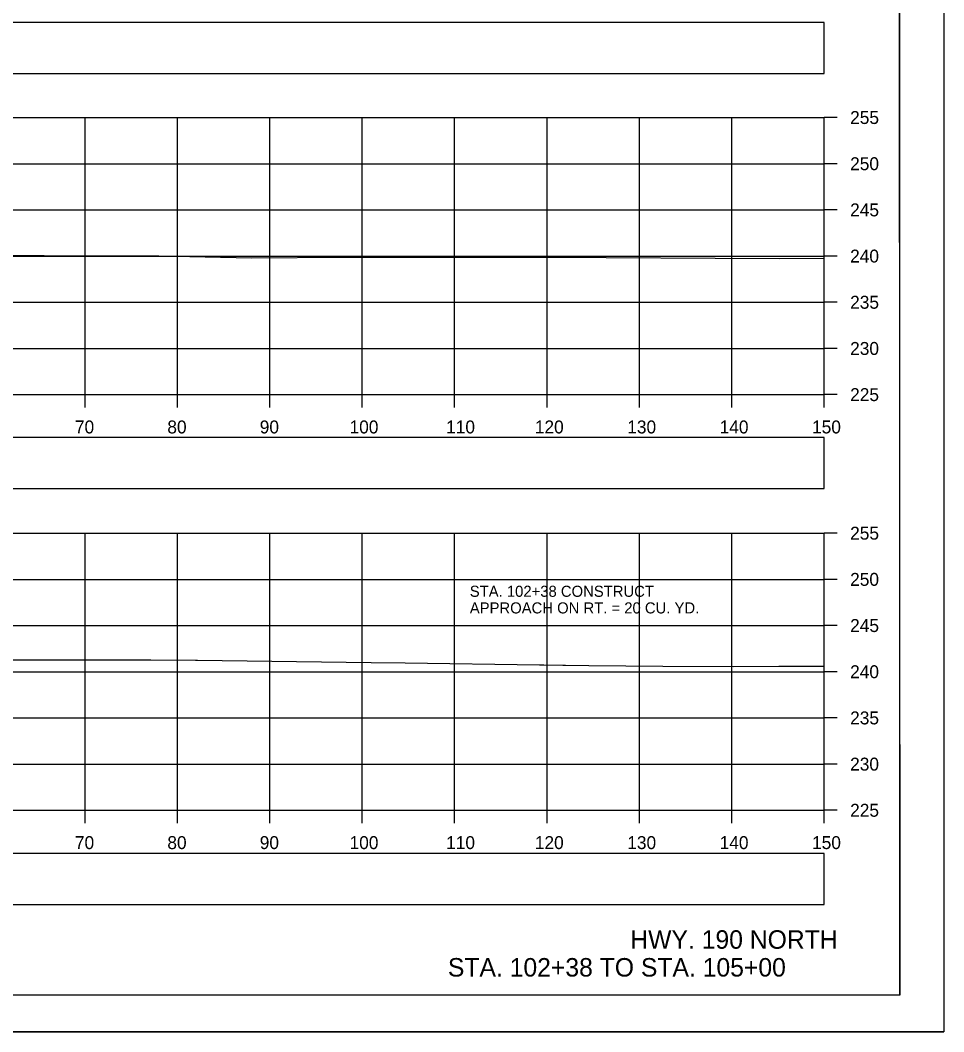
# Model space of a CAD drawing. Extents: x 1369627 to 1374022, y 380035 to 398173.
# Drawn here: x 1370242.2 to 1370342.2, y 380248.2 to 380357.7 of the extents above; entities that cross this region are included whole.
import ezdxf

# ---------------------------------------------------------------- set-up
doc = ezdxf.new("R2010")
doc.units = 0
for name, color, linetype in [('Default', 7, 'Continuous'), ('R_Axis', 7, 'Continuous'), ('R_Axis Annot', 7, 'Continuous'), ('R_Border', 7, 'Continuous'), ('R_Draft', 7, 'Continuous'), ('R_Exist Surface', 7, 'Continuous'), ('R_Grid', 7, 'Continuous'), ('R_No Plot', 7, 'Continuous'), ('R_Water', 7, 'Continuous')]:
    doc.layers.add(name, color=color, linetype=linetype)

msp = doc.modelspace()

# ---------------------------------------------------------------- linework, layer by layer
at = {"layer": 'Default'}
for points in [[(1370029.24, 380351.95), (1370329.24, 380351.95), (1370329.24, 380357.47), (1370029.24, 380357.47)], [(1370029.24, 380307.01), (1370329.24, 380307.01), (1370329.24, 380312.54), (1370029.24, 380312.54)], [(1370029.24, 380261.98), (1370329.24, 380261.98), (1370329.24, 380267.5), (1370029.24, 380267.5)]]:
    msp.add_lwpolyline(points, close=True, dxfattribs=at)
at = {"layer": 'R_Axis'}
for p, q in [((1370329.24, 380317.19), (1370329.24, 380347.19)), ((1370330.64, 380347.19), (1370329.24, 380347.19)), ((1370330.64, 380342.19), (1370329.24, 380342.19)), ((1370330.64, 380337.19), (1370329.24, 380337.19)), ((1370330.64, 380332.19), (1370329.24, 380332.19)), ((1370330.64, 380327.19), (1370329.24, 380327.19)), ((1370330.64, 380322.19), (1370329.24, 380322.19)), ((1370029.24, 380317.19), (1370329.24, 380317.19)), ((1370249.24, 380315.79), (1370249.24, 380317.19)), ((1370259.24, 380315.79), (1370259.24, 380317.19)), ((1370269.24, 380315.79), (1370269.24, 380317.19)), ((1370279.24, 380315.79), (1370279.24, 380317.19)), ((1370289.24, 380315.79), (1370289.24, 380317.19)), ((1370299.24, 380315.79), (1370299.24, 380317.19)), ((1370309.24, 380315.79), (1370309.24, 380317.19)), ((1370319.24, 380315.79), (1370319.24, 380317.19)), ((1370329.24, 380315.79), (1370329.24, 380317.19)), ((1370330.64, 380317.19), (1370329.24, 380317.19)), ((1370329.24, 380272.19), (1370329.24, 380302.19)), ((1370330.64, 380302.19), (1370329.24, 380302.19)), ((1370330.64, 380297.19), (1370329.24, 380297.19)), ((1370330.64, 380292.19), (1370329.24, 380292.19)), ((1370330.64, 380287.19), (1370329.24, 380287.19)), ((1370330.64, 380282.19), (1370329.24, 380282.19)), ((1370330.64, 380277.19), (1370329.24, 380277.19)), ((1370029.24, 380272.19), (1370329.24, 380272.19)), ((1370249.24, 380270.79), (1370249.24, 380272.19)), ((1370259.24, 380270.79), (1370259.24, 380272.19)), ((1370269.24, 380270.79), (1370269.24, 380272.19)), ((1370279.24, 380270.79), (1370279.24, 380272.19)), ((1370289.24, 380270.79), (1370289.24, 380272.19)), ((1370299.24, 380270.79), (1370299.24, 380272.19)), ((1370309.24, 380270.79), (1370309.24, 380272.19)), ((1370319.24, 380270.79), (1370319.24, 380272.19)), ((1370329.24, 380270.79), (1370329.24, 380272.19)), ((1370330.64, 380272.19), (1370329.24, 380272.19))]:
    msp.add_line(p, q, dxfattribs=at)
at = {"layer": 'R_Border'}
for q in [(1370337.42, 380457.65), (1370021.24, 380252.19)]:
    msp.add_line((1370337.42, 380252.19), q, dxfattribs=at)
at = {"layer": 'R_Exist Surface'}
for points in [[(1370240.95, 380332.3), (1370248.69, 380332.2), (1370257.05, 380332.21), (1370257.13, 380332.21), (1370257.24, 380332.21), (1370267.27, 380332.01), (1370277.18, 380332.09), (1370287.06, 380332.08), (1370291.38, 380332.06), (1370301.45, 380332.06), (1370305.63, 380332.03), (1370317.45, 380331.96), (1370324.4, 380331.94), (1370329.24, 380331.96)], [(1370233.09, 380288.49), (1370246.11, 380288.48), (1370246.74, 380288.48), (1370247.13, 380288.48), (1370256.38, 380288.47), (1370261.19, 380288.43), (1370261.29, 380288.43), (1370261.34, 380288.43), (1370261.43, 380288.43), (1370277.51, 380288.22), (1370280.2, 380288.18), (1370283.88, 380288.14), (1370298.44, 380287.95), (1370298.88, 380287.92), (1370300.94, 380287.89), (1370301.25, 380287.89), (1370303.78, 380287.86), (1370311.77, 380287.81), (1370319.45, 380287.76), (1370324.33, 380287.8), (1370327.04, 380287.79), (1370329.24, 380287.79)]]:
    msp.add_lwpolyline(points, dxfattribs=at)
at = {"layer": 'R_Grid'}
for p, q in [((1370029.24, 380347.19), (1370329.24, 380347.19)), ((1370249.24, 380317.19), (1370249.24, 380347.19)), ((1370259.24, 380317.19), (1370259.24, 380347.19)), ((1370269.24, 380317.19), (1370269.24, 380347.19)), ((1370279.24, 380317.19), (1370279.24, 380347.19)), ((1370289.24, 380317.19), (1370289.24, 380347.19)), ((1370299.24, 380317.19), (1370299.24, 380347.19)), ((1370309.24, 380317.19), (1370309.24, 380347.19)), ((1370319.24, 380317.19), (1370319.24, 380347.19)), ((1370329.24, 380317.19), (1370329.24, 380347.19)), ((1370029.24, 380342.19), (1370329.24, 380342.19)), ((1370029.24, 380337.19), (1370329.24, 380337.19)), ((1370029.24, 380332.19), (1370329.24, 380332.19)), ((1370029.24, 380327.19), (1370329.24, 380327.19)), ((1370029.24, 380322.19), (1370329.24, 380322.19)), ((1370029.24, 380317.19), (1370329.24, 380317.19)), ((1370029.24, 380302.19), (1370329.24, 380302.19)), ((1370249.24, 380272.19), (1370249.24, 380302.19)), ((1370259.24, 380272.19), (1370259.24, 380302.19)), ((1370269.24, 380272.19), (1370269.24, 380302.19)), ((1370279.24, 380272.19), (1370279.24, 380302.19)), ((1370289.24, 380272.19), (1370289.24, 380302.19)), ((1370299.24, 380272.19), (1370299.24, 380302.19)), ((1370309.24, 380272.19), (1370309.24, 380302.19)), ((1370319.24, 380272.19), (1370319.24, 380302.19)), ((1370329.24, 380272.19), (1370329.24, 380302.19)), ((1370029.24, 380297.19), (1370329.24, 380297.19)), ((1370029.24, 380292.19), (1370329.24, 380292.19)), ((1370029.24, 380287.19), (1370329.24, 380287.19)), ((1370029.24, 380282.19), (1370329.24, 380282.19)), ((1370029.24, 380277.19), (1370329.24, 380277.19)), ((1370029.24, 380272.19), (1370329.24, 380272.19))]:
    msp.add_line(p, q, dxfattribs=at)
at = {"layer": 'R_No Plot'}
msp.add_line((1370008.84, 380248.22), (1370342.17, 380248.22), dxfattribs=at)
for points in [[(1370008.83, 380461.55), (1370342.17, 380461.55), (1370342.17, 380248.21), (1370008.83, 380248.21)], [(1370255.16, 380457.65), (1370274.78, 380457.65), (1370274.78, 380447.77), (1370290.89, 380447.77), (1370314.09, 380447.77), (1370314.09, 380415.1), (1370337.3, 380415.1), (1370337.42, 380252.19), (1370021.24, 380252.19), (1370021.24, 380457.65)]]:
    msp.add_lwpolyline(points, close=True, dxfattribs=at)

# ---------------------------------------------------------------- texts
at = {"layer": 'R_Axis Annot'}
for s, p in [('255', (1370332.04, 380346.49)), ('250', (1370332.04, 380341.49)), ('245', (1370332.04, 380336.49)), ('240', (1370332.04, 380331.49)), ('235', (1370332.04, 380326.49)), ('230', (1370332.04, 380321.49)), ('225', (1370332.04, 380316.49)), ('70', (1370248.15, 380312.99)), ('80', (1370258.15, 380312.99)), ('90', (1370268.15, 380312.99)), ('100', (1370277.87, 380312.99)), ('110', (1370288.32, 380312.99)), ('120', (1370297.92, 380312.99)), ('130', (1370307.92, 380312.99)), ('140', (1370317.92, 380312.99)), ('150', (1370327.92, 380312.99)), ('255', (1370332.04, 380301.49)), ('250', (1370332.04, 380296.49)), ('245', (1370332.04, 380291.49)), ('240', (1370332.04, 380286.49)), ('235', (1370332.04, 380281.49)), ('230', (1370332.04, 380276.49)), ('225', (1370332.04, 380271.49)), ('70', (1370248.15, 380267.99)), ('80', (1370258.15, 380267.99)), ('90', (1370268.15, 380267.99)), ('100', (1370277.87, 380267.99)), ('110', (1370288.32, 380267.99)), ('120', (1370297.92, 380267.99)), ('130', (1370307.92, 380267.99)), ('140', (1370317.92, 380267.99)), ('150', (1370327.92, 380267.99))]:
    msp.add_text(s, height=1.4, dxfattribs=at).set_placement(p)
at = {"layer": 'R_Draft'}
for s, p in [('HWY. 190 NORTH', (1370308.25, 380257.2)), ('STA. 102+38 TO STA. 105+00', (1370288.51, 380254.19))]:
    msp.add_text(s, height=2, dxfattribs=at).set_placement(p)
at = {"layer": 'R_Water'}
for s, p in [('STA. 102+38 CONSTRUCT', (1370290.88, 380295.3)), ('APPROACH ON RT. = 20 CU. YD.', (1370290.88, 380293.5))]:
    msp.add_text(s, height=1.2, dxfattribs=at).set_placement(p)

doc.saveas('drawing.dxf')
